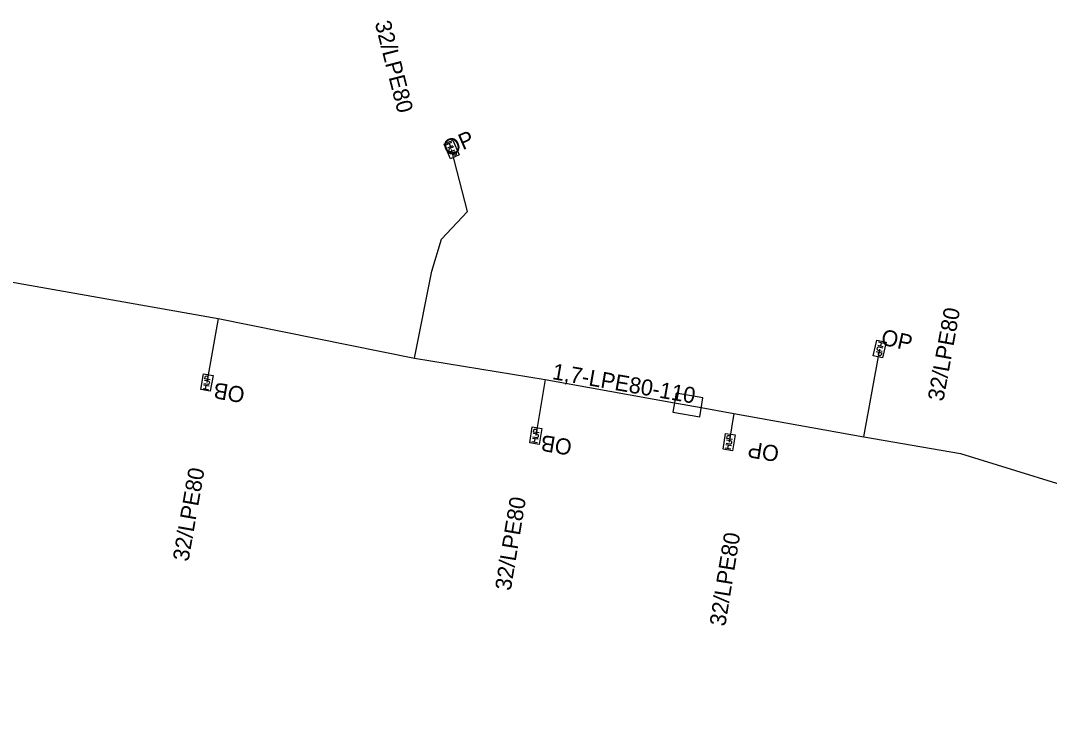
# Model space of a CAD drawing. Extents: x -762509 to -761250, y -1153000 to -1152256.
# Drawn here: x -761437.4 to -761373.3, y -1152558.6 to -1152514.8 of the extents above; entities that cross this region are included whole.
import ezdxf

# ---------------------------------------------------------------- set-up
doc = ezdxf.new("R2010")
doc.units = 0
for name, color, linetype in [('Vrstva 21', 7, 'Continuous'), ('Vrstva 29', 7, 'Continuous'), ('Vrstva 31', 7, 'Continuous'), ('Vrstva 32', 7, 'Continuous')]:
    doc.layers.add(name, color=color, linetype=linetype)

msp = doc.modelspace()

# ---------------------------------------------------------------- linework, layer by layer
at = {"layer": 'Vrstva 21'}
msp.add_lwpolyline([(-761456.83, -1152527.87), (-761448.25, -1152529.25), (-761446.58, -1152529.57), (-761444.73, -1152529.87), (-761425.09, -1152533.35), (-761412.86, -1152535.83), (-761404.73, -1152537.14), (-761396.67, -1152538.6), (-761395, -1152538.89), (-761392.98, -1152539.26), (-761384.89, -1152540.72), (-761378.87, -1152541.76), (-761369.46, -1152544.68), (-761366.06, -1152546), (-761363.94, -1152546.96), (-761363.78, -1152547.02), (-761358.42, -1152549.62), (-761356.97, -1152550.5), (-761355.51, -1152551.26), (-761353.56, -1152552.55), (-761349.19, -1152555.34), (-761336.19, -1152563.79)], dxfattribs=at)
at = {"layer": 'Vrstva 29'}
msp.add_lwpolyline([(-761396.77, -1152539.19), (-761395.1, -1152539.48), (-761394.9, -1152538.3), (-761396.57, -1152538.01)], close=True, dxfattribs=at)
at = {"layer": 'Vrstva 31'}
for points in [[(-761412.86, -1152535.83), (-761411.79, -1152530.39), (-761411.17, -1152528.4), (-761409.57, -1152526.67), (-761410.55, -1152522.82)], [(-761425.09, -1152533.35), (-761425.79, -1152537.34)], [(-761384.89, -1152540.72), (-761383.89, -1152535.25)], [(-761404.73, -1152537.14), (-761405.31, -1152540.65)], [(-761392.98, -1152539.26), (-761393.27, -1152541.05)]]:
    msp.add_lwpolyline(points, dxfattribs=at)
at = {"layer": 'Vrstva 32'}
for p, q in [((-761410.548, -1152522.383), (-761410.869, -1152522.522)), ((-761410.789, -1152522.707), (-761410.468, -1152522.568)), ((-761410.7, -1152522.449), (-761410.62, -1152522.633)), ((-761410.631, -1152523.073), (-761410.31, -1152522.934)), ((-761384.105, -1152535.406), (-761383.764, -1152535.483)), ((-761384.016, -1152535.017), (-761383.675, -1152535.094)), ((-761383.63, -1152534.898), (-761383.972, -1152534.821)), ((-761383.791, -1152534.862), (-761383.836, -1152535.058)), ((-761425.583, -1152537.173), (-761425.928, -1152537.113)), ((-761426.032, -1152537.704), (-761425.687, -1152537.764)), ((-761425.652, -1152537.566), (-761425.997, -1152537.506)), ((-761425.869, -1152537.732), (-761425.835, -1152537.534)), ((-761405.105, -1152540.481), (-761405.45, -1152540.424)), ((-761405.548, -1152541.016), (-761405.203, -1152541.073)), ((-761405.17, -1152540.875), (-761405.515, -1152540.818)), ((-761405.385, -1152541.043), (-761405.353, -1152540.845)), ((-761393.065, -1152540.88), (-761393.41, -1152540.824)), ((-761393.506, -1152541.416), (-761393.161, -1152541.472)), ((-761393.129, -1152541.274), (-761393.474, -1152541.218)), ((-761393.344, -1152541.443), (-761393.311, -1152541.244))]:
    msp.add_line(p, q, dxfattribs=at)
for points in [[(-761410.473, -1152522.242), (-761410.076, -1152523.159), (-761410.626, -1152523.398), (-761411.024, -1152522.48), (-761410.473, -1152522.242)], [(-761410.429, -1152522.658), (-761410.659, -1152522.758), (-761410.699, -1152522.791), (-761410.717, -1152522.832), (-761410.716, -1152522.877), (-761410.704, -1152522.904), (-761410.672, -1152522.936), (-761410.63, -1152522.949), (-761410.579, -1152522.943), (-761410.349, -1152522.843)], [(-761410.31, -1152522.934), (-761410.258, -1152523.053), (-761410.257, -1152523.098), (-761410.266, -1152523.118), (-761410.29, -1152523.144), (-761410.336, -1152523.164), (-761410.372, -1152523.165), (-761410.393, -1152523.157), (-761410.425, -1152523.125), (-761410.477, -1152523.006)], [(-761383.486, -1152534.829), (-761383.709, -1152535.804), (-761384.294, -1152535.67), (-761384.071, -1152534.695), (-761383.486, -1152534.829)], [(-761383.697, -1152535.191), (-761383.942, -1152535.135), (-761383.993, -1152535.138), (-761384.032, -1152535.161), (-761384.058, -1152535.198), (-761384.064, -1152535.226), (-761384.057, -1152535.271), (-761384.031, -1152535.307), (-761383.987, -1152535.331), (-761383.742, -1152535.387)], [(-761383.764, -1152535.483), (-761383.793, -1152535.61), (-761383.819, -1152535.647), (-761383.838, -1152535.658), (-761383.873, -1152535.665), (-761383.922, -1152535.654), (-761383.951, -1152535.633), (-761383.963, -1152535.614), (-761383.97, -1152535.57), (-761383.941, -1152535.443)], [(-761426.172, -1152537.781), (-761425.999, -1152536.796), (-761425.408, -1152536.899), (-761425.581, -1152537.884), (-761426.172, -1152537.781)], [(-761425.98, -1152537.408), (-761425.733, -1152537.451), (-761425.682, -1152537.446), (-761425.644, -1152537.421), (-761425.62, -1152537.383), (-761425.615, -1152537.354), (-761425.625, -1152537.31), (-761425.652, -1152537.276), (-761425.698, -1152537.254), (-761425.945, -1152537.21)], [(-761425.928, -1152537.113), (-761425.906, -1152536.985), (-761425.882, -1152536.946), (-761425.863, -1152536.934), (-761425.828, -1152536.926), (-761425.779, -1152536.935), (-761425.749, -1152536.954), (-761425.736, -1152536.972), (-761425.726, -1152537.016), (-761425.749, -1152537.144)], [(-761405.688, -1152541.095), (-761405.525, -1152540.108), (-761404.933, -1152540.206), (-761405.096, -1152541.192), (-761405.688, -1152541.095)], [(-761405.499, -1152540.72), (-761405.252, -1152540.761), (-761405.201, -1152540.755), (-761405.163, -1152540.73), (-761405.14, -1152540.692), (-761405.135, -1152540.663), (-761405.145, -1152540.619), (-761405.173, -1152540.585), (-761405.219, -1152540.563), (-761405.467, -1152540.522)], [(-761405.45, -1152540.424), (-761405.429, -1152540.296), (-761405.406, -1152540.257), (-761405.387, -1152540.245), (-761405.353, -1152540.237), (-761405.303, -1152540.245), (-761405.273, -1152540.264), (-761405.26, -1152540.282), (-761405.25, -1152540.326), (-761405.271, -1152540.454)], [(-761393.646, -1152541.495), (-761393.486, -1152540.508), (-761392.894, -1152540.604), (-761393.054, -1152541.591), (-761393.646, -1152541.495)], [(-761393.458, -1152541.12), (-761393.211, -1152541.16), (-761393.16, -1152541.154), (-761393.123, -1152541.129), (-761393.099, -1152541.09), (-761393.094, -1152541.062), (-761393.104, -1152541.018), (-761393.132, -1152540.984), (-761393.179, -1152540.962), (-761393.426, -1152540.922)], [(-761393.41, -1152540.824), (-761393.39, -1152540.696), (-761393.366, -1152540.657), (-761393.348, -1152540.645), (-761393.313, -1152540.636), (-761393.264, -1152540.644), (-761393.233, -1152540.663), (-761393.22, -1152540.681), (-761393.21, -1152540.725), (-761393.231, -1152540.853)]]:
    msp.add_lwpolyline(points, dxfattribs=at)

# ---------------------------------------------------------------- texts
at = {"layer": 'Vrstva 29'}
msp.add_text('1,7-LPE80-110', height=1, rotation=350.14867, dxfattribs=at).set_placement((-761404.33, -1152537.12))
at = {"layer": 'Vrstva 31'}
for rotation, p in [(284.2811, (-761415.34, -1152514.92)), (284.2811, (-761415.34, -1152514.92)), (79.63986, (-761379.93, -1152538.55)), (79.63986, (-761379.93, -1152538.55)), (80.04937, (-761426.94, -1152548.53)), (80.04937, (-761426.94, -1152548.53)), (80.61711, (-761406.87, -1152550.35)), (80.61711, (-761406.87, -1152550.35)), (80.7974, (-761393.51, -1152552.57)), (80.7974, (-761393.51, -1152552.57))]:
    msp.add_text('32/LPE80', height=1, rotation=rotation, dxfattribs=at).set_placement(p)
at = {"layer": 'Vrstva 32'}
for s, rotation, p in [('OP', 23.41775, (-761410.81, -1152523.28)), ('OP', 23.41775, (-761410.81, -1152523.28)), ('OP', 347.16053, (-761383.87, -1152534.96)), ('OP', 347.16053, (-761383.87, -1152534.96)), ('OB', 170.04937, (-761423.37, -1152537.65)), ('OB', 170.04937, (-761423.37, -1152537.65)), ('OB', 170.61711, (-761403, -1152540.91)), ('OB', 170.61711, (-761403, -1152540.91)), ('OP', 170.7974, (-761390.1, -1152541.31)), ('OP', 170.7974, (-761390.1, -1152541.31))]:
    msp.add_text(s, height=1, rotation=rotation, dxfattribs=at).set_placement(p)

doc.saveas('drawing.dxf')
